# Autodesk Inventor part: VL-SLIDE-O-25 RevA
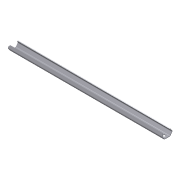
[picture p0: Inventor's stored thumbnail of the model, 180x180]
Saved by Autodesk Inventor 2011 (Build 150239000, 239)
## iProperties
Created: 2007-09
Part Number: VL-SLIDE-O-25 RevA
Material: Steel
Document SubType Name: Modeling
Density: 7.85 g/cm^3
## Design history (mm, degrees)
feature "Base1"
workplane "Work Plane1"
body "Solid1"
